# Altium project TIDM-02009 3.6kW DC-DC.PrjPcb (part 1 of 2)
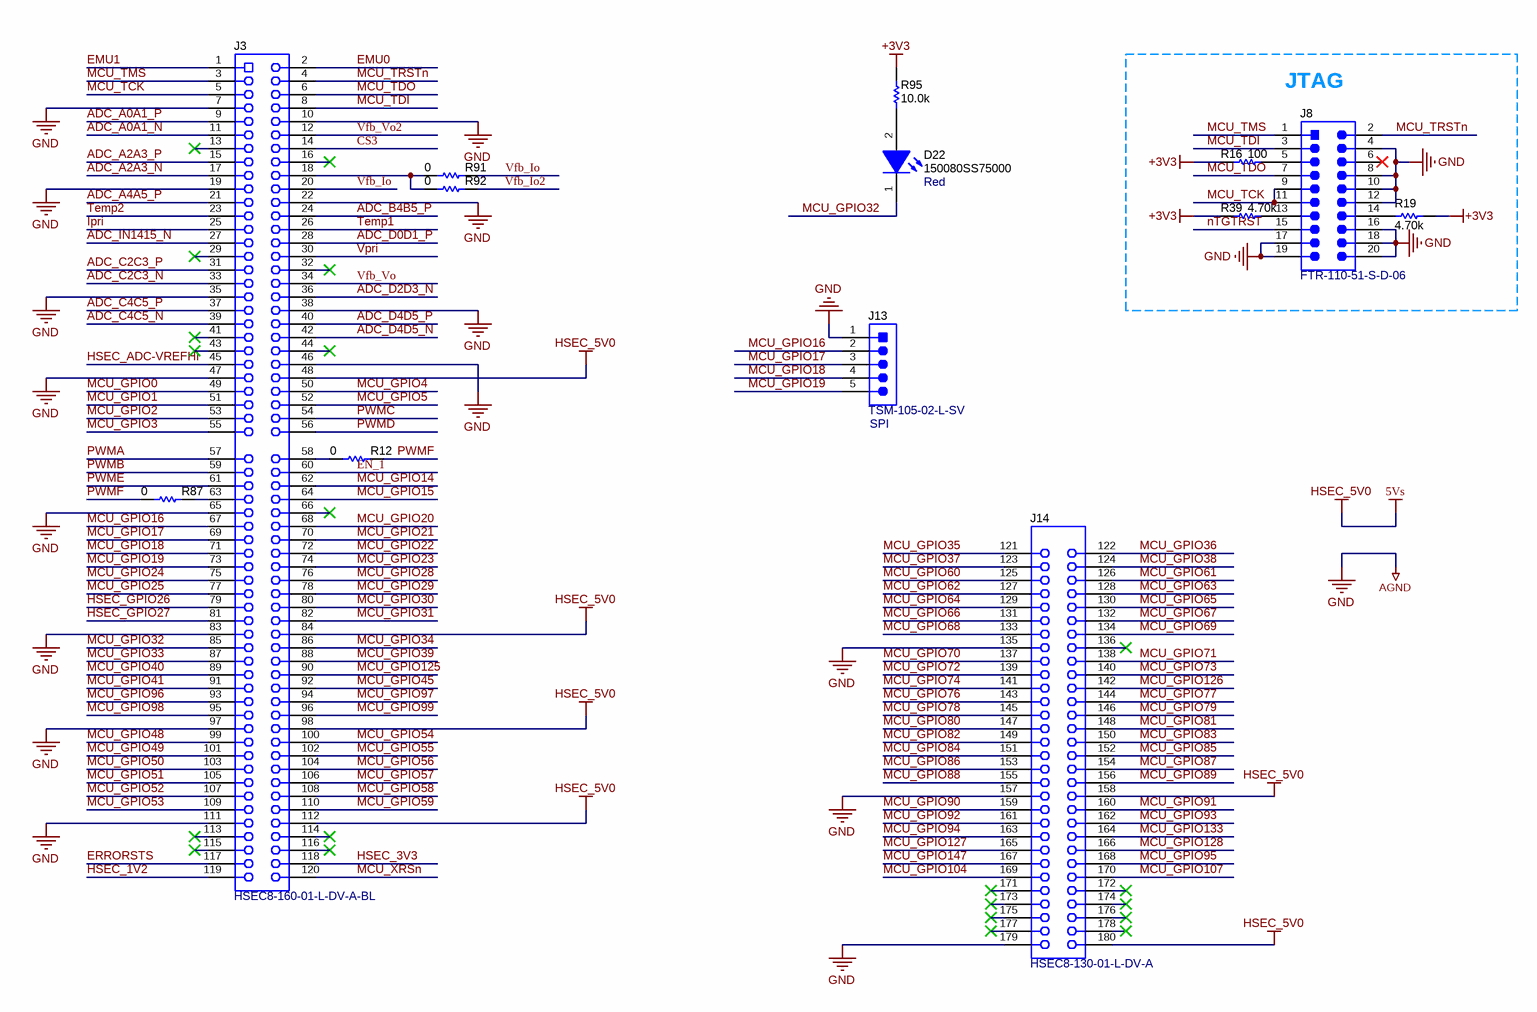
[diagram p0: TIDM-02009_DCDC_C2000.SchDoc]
CopyrightYear: 2020; PCB_Layout: H. Zhang, J. Cao, X. Gong; PCB_Rev: E2; PRJ_Customer: Public Release; PRJ_Engineer: H. Zhang; PRJ_Number: TIDM-02009; PRJ_Title: TIDM-02009 3.6kW DC-DC; SCH_Rev: E2; TechSupport: http://www.ti.com/support; TID: TIDM-02009
4 sheets, 301 parts. Net scope: global (net labels, ports and power ports of the same name join across sheets).
Board file: TIDM-02009 3.6kW DC-DC.PcbDoc
Sheets:
  TIDM-02009_DCDC_C2000.SchDoc
  TIDM-02009_DCDC_Control.SchDoc
  TIDM-02009_DCDC_Hardware.SchDoc
  TIDM-02009_DCDC_Power Stage.SchDoc

## Sheet TIDM-02009_DCDC_C2000.SchDoc
size A3; Date: Not shown in title block; ApprovedBy: Not shown in title block; CheckedBy: Not shown in title block; Author: Not shown in title block; CompanyName: Not shown in title block; Engineer: Not shown in title block; Organization: Not shown in title block; Address1: Not shown in title block; Address2: Not shown in title block; Address3: Not shown in title block; Address4: Not shown in title block; DocumentNumber: 2; Revision: Use project parameter SCH_Rev; SheetNumber: 2; SheetTotal: 3; PageSetup: Record=PageOptions¦CenterHorizontal=True¦CenterVertical=True¦PrintScale=1.00¦XCorrection=1.00¦YCorrection=1.00¦PrintKind=0¦BorderSize=5000000¦LeftOffset=0¦BottomOffset=0¦Orientation=2¦PaperLength=1000¦PaperWidth=1000¦Scale=100¦PaperSource=15¦PrintQuality=600¦MediaType=1¦DitherType=10¦PaperKind=Letter¦PrintScaleMode=1

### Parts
D22  150080SS75000  value Red  [WL-SMCW_RED_0805]
J3  HSEC8-160-01-L-DV-A-BL  [controlCARD-120HSEC]
J8  FTR-110-51-S-D-06  [Samtec_FTR-110-51-x-D-06]
J13  TSM-105-02-L-SV  [Samtec_TSM-105-02-x-SV]
J14  HSEC8-130-01-L-DV-A  [controlCARD-180HSEC-60pinAddon]
R12  ValueDisplayed: 0  [0603]  (hidden comment: RCS06030000Z0EA)
R16  ValueDisplayed: 100  [0603]  (hidden comment: ERJ-3EKF1000V)
R19  ValueDisplayed: 4.70k  [0603]  (hidden comment: RC0603FR-074K7L)
R39  ValueDisplayed: 4.70k  [0603]  (hidden comment: RC0603FR-074K7L)
R87  ValueDisplayed: 0  [0603]  (hidden comment: RCS06030000Z0EA)
R91  ValueDisplayed: 0  [0603]  (hidden comment: RCS06030000Z0EA)
R92  ValueDisplayed: 0  [0603]  (hidden comment: RCS06030000Z0EA)
R95  ValueDisplayed: 10.0k  [0603]  (hidden comment: RC0603FR-0710KL)

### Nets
5Vs: J3.48 J3.84 J3.98 J3.112 J14.158 J14.180  [also labelled HSEC_5V0]
+3V3: R16.1 R19.2 R39.1 R95.2
AGND: J3.7 J3.10 J3.19 J3.22 J3.35 J3.38 J3.46 J3.47 J3.65 J3.83 J3.97 J3.111 J8.4 J8.8 J8.10 J8.12 J8.16 J8.17 J8.18 J8.19 J8.20 J13.1 J14.135 J14.157 J14.179  [also labelled GND]
ADC_A0A1_N: J3.11
ADC_A0A1_P: J3.9
ADC_A2A3_N: J3.17
ADC_A2A3_P: J3.15
ADC_A4A5_P: J3.21
ADC_B4B5_P: J3.24
ADC_C2C3_N: J3.33
ADC_C2C3_P: J3.31
ADC_C4C5_N: J3.39
ADC_C4C5_P: J3.37
ADC_D0D1_P: J3.28
ADC_D2D3_N: J3.36
ADC_D4D5_N: J3.42
ADC_D4D5_P: J3.40
ADC_IN1415_N: J3.27
CS3: J3.14
EMU0: J3.2
EMU1: J3.1
EN_1: J3.60
ERRORSTS: J3.117
HSEC_1V2: J3.119
HSEC_3V3: J3.118
HSEC_ADC-VREFHI: J3.45
HSEC_GPIO26: J3.79
HSEC_GPIO27: J3.81
Ipri: J3.25
MCU_GPIO0: J3.49
MCU_GPIO1: J3.51
MCU_GPIO2: J3.53
MCU_GPIO3: J3.55
MCU_GPIO4: J3.50
MCU_GPIO5: J3.52
MCU_GPIO14: J3.62
MCU_GPIO15: J3.64
MCU_GPIO16: J3.67 J13.2
MCU_GPIO17: J3.69 J13.3
MCU_GPIO18: J3.71 J13.4
MCU_GPIO19: J3.73 J13.5
MCU_GPIO20: J3.68
MCU_GPIO21: J3.70
MCU_GPIO22: J3.72
MCU_GPIO23: J3.74
MCU_GPIO24: J3.75
MCU_GPIO25: J3.77
MCU_GPIO28: J3.76
MCU_GPIO29: J3.78
MCU_GPIO30: J3.80
MCU_GPIO31: J3.82
MCU_GPIO32: D22.1(K) J3.85
MCU_GPIO33: J3.87
MCU_GPIO34: J3.86
MCU_GPIO35: J14.121
MCU_GPIO36: J14.122
MCU_GPIO37: J14.123
MCU_GPIO38: J14.124
MCU_GPIO39: J3.88
MCU_GPIO40: J3.89
MCU_GPIO41: J3.91
MCU_GPIO45: J3.92
MCU_GPIO48: J3.99
MCU_GPIO49: J3.101
MCU_GPIO50: J3.103
MCU_GPIO51: J3.105
MCU_GPIO52: J3.107
MCU_GPIO53: J3.109
MCU_GPIO54: J3.100
MCU_GPIO55: J3.102
MCU_GPIO56: J3.104
MCU_GPIO57: J3.106
MCU_GPIO58: J3.108
MCU_GPIO59: J3.110
MCU_GPIO60: J14.125
MCU_GPIO61: J14.126
MCU_GPIO62: J14.127
MCU_GPIO63: J14.128
MCU_GPIO64: J14.129
MCU_GPIO65: J14.130
MCU_GPIO66: J14.131
MCU_GPIO67: J14.132
MCU_GPIO68: J14.133
MCU_GPIO69: J14.134
MCU_GPIO70: J14.137
MCU_GPIO71: J14.138
MCU_GPIO72: J14.139
MCU_GPIO73: J14.140
MCU_GPIO74: J14.141
MCU_GPIO76: J14.143
MCU_GPIO77: J14.144
MCU_GPIO78: J14.145
MCU_GPIO79: J14.146
MCU_GPIO80: J14.147
MCU_GPIO81: J14.148
MCU_GPIO82: J14.149
MCU_GPIO83: J14.150
MCU_GPIO84: J14.151
MCU_GPIO85: J14.152
MCU_GPIO86: J14.153
MCU_GPIO87: J14.154
MCU_GPIO88: J14.155
MCU_GPIO89: J14.156
MCU_GPIO90: J14.159
MCU_GPIO91: J14.160
MCU_GPIO92: J14.161
MCU_GPIO93: J14.162
MCU_GPIO94: J14.163
MCU_GPIO95: J14.168
MCU_GPIO96: J3.93
MCU_GPIO97: J3.94
MCU_GPIO98: J3.95
MCU_GPIO99: J3.96
MCU_GPIO104: J14.169
MCU_GPIO107: J14.170
MCU_GPIO125: J3.90
MCU_GPIO126: J14.142
MCU_GPIO127: J14.165
MCU_GPIO128: J14.166
MCU_GPIO133: J14.164
MCU_GPIO147: J14.167
MCU_TCK: J3.5 J8.9 J8.11
MCU_TDI: J3.8 J8.3
MCU_TDO: J3.6 J8.7
MCU_TMS: J3.3 J8.1
MCU_TRSTn: J3.4 J8.2
MCU_XRSn: J3.120
nTGTRST: J8.15
PWMA: J3.57
PWMB: J3.59
PWMC: J3.54
PWMD: J3.56
PWME: J3.61
PWMF: R12.2 R87.1
Temp1: J3.26
Temp2: J3.23
Vfb_Io: J3.20 R91.2
Vfb_Io2: R92.2
Vfb_Vo: J3.34
Vfb_Vo2: J3.12
Vpri: J3.30
NetD22_2: D22.2(A) R95.1
NetJ3_18: J3.18 R91.1 R92.1
NetJ3_58: J3.58 R12.1
NetJ3_63: J3.63 R87.2
NetJ8_5: J8.5 R16.2
NetJ8_13: J8.13 R39.2
NetJ8_14: J8.14 R19.1

Not connected (* = marked no-connect by the designer): J3 13* 16* 29* 32* 41* 43* 44* 66* 113* 114* 115* 116*; J8 6*; J14 136* 171* 172* 173* 174* 175* 176* 177* 178*

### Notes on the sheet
- (near J8) JTAG
- (near J13) SPI

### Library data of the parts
D22 = CMP-0002951-1: LED, Red, SMD; Manufacturer: Wurth Elektronik; Io_A: 30mA; Power_TotalModule: 72mW; Vr_V: 5V; Tjmax_C: 85°C; Value1: 0.072W; U/M: EA; Angle: 140; Ir_A: 25µA; Vf_V: 1.9V; Type: AlInGaP
J3 = CMP-0003814-2: C2000 controlCARD-120HSEC connector, SMT; Manufacturer: Samtec; Note: The pin numbering does not match Samtec datasheet
J8 = CMP-0075640-2: Header, 1.27mm, 10x2, Tin, SMT; Manufacturer: Samtec; Pitch_mm: 1.27; Gender: Male; Cert_UL: Y; Green_REACh: Passed; Current_A: 3.1A; Shrouded: N; RowSpacing_mm: 2.54; Green_Lifecycle: Active; Row_Count: 2
J13 = CMP-0081122-1: Header, 2.54mm, 5x1, Gold with Tin tail, SMT; Manufacturer: Samtec; Pitch_mm: 2.54; Gender: Male; Cert_UL: Y; Current_A: 5.4A; Voltage_V: 475V; Shrouded: N; Row_Count: 1
J14 = CMP-0003859-2: C2000 controlCARD-180HSEC (60-pin addon) connector, SMT; Manufacturer: Samtec; Note: The pin numbering does not match Samtec datasheet
R12 R87 R91 R92 = CMP-0081973-1: RES, 0, 0%, 0.25 W, AEC-Q200 Grade 0, 0603; Manufacturer: Vishay-Dale; SizeAreaWB_mm2: 4.68; SizeArea_mm2: 1.28; AEC Qualified: Y; AEC Category: Q200; Value: 0; SizeZ_mm: 1; SizeY_mm: 0.8; Power_W: 250mW; Value2: 0.25W; SizeX_mm: 1.6
R16 = CMP-0022679-3: RES, 100, 1%, 0.1 W, AEC-Q200 Grade 0, 0603; Manufacturer: Panasonic; Power_W: 100mW; TempCo: 100 ppm/C; Value_Code: 100R; U/M: EA; Value: 100; EIA_Code: E96; SizeX_mm: 1.6; SizeY_mm: 0.8; SizeZ_mm: 1; Value2: 0.1W; SizeArea_mm2: 1.28; AEC Qualified: Y; AEC Grade: 0; AEC Category: Q200
R19 R39 = CMP-0023153-5: RES, 4.70 k, 1%, 0.1 W, 0603; Manufacturer: Yageo; Power_W: 100mW; TempCo: 100 ppm/C; Value_Code: 4k70; Value: 4.70k; Res_ohm: 4.7k; SizeX_mm: 1.6; SizeY_mm: 0.8; SizeZ_mm: 1; Value2: 0.1W; SizeArea_mm2: 1.28; AEC Qualified: N; VDC_V: 75V; AEC Category: Q200; SizeAreaWB_mm2: 4.68
R95 = CMP-0022746-5: RES, 10.0 k, 1%, 0.1 W, 0603; Manufacturer: Yageo; Power_W: 100mW; TempCo: 100 ppm/C; Value_Code: 10k0; Value: 10.0k; EIA_Code: E96; Res_ohm: 10k; SizeX_mm: 1.6; SizeY_mm: 0.8; SizeZ_mm: 1; Value2: 0.1W; SizeArea_mm2: 1.28; AEC Qualified: N; VDC_V: 75V; AEC Category: Q200; SizeAreaWB_mm2: 4.68

## Sheet TIDM-02009_DCDC_Control.SchDoc
size A2; PageSetup: Record=PageOptions¦CenterHorizontal=True¦CenterVertical=True¦PrintScale=0.69¦XCorrection=1.00¦YCorrection=1.00¦PrintKind=0¦BorderSize=5000000¦LeftOffset=0¦BottomOffset=0¦Orientation=2¦PaperLength=1000¦PaperWidth=1000¦Scale=100¦PaperSource=15¦PrintQuality=600¦MediaType=1¦DitherType=10¦PaperKind=Letter¦PrintScaleMode=1
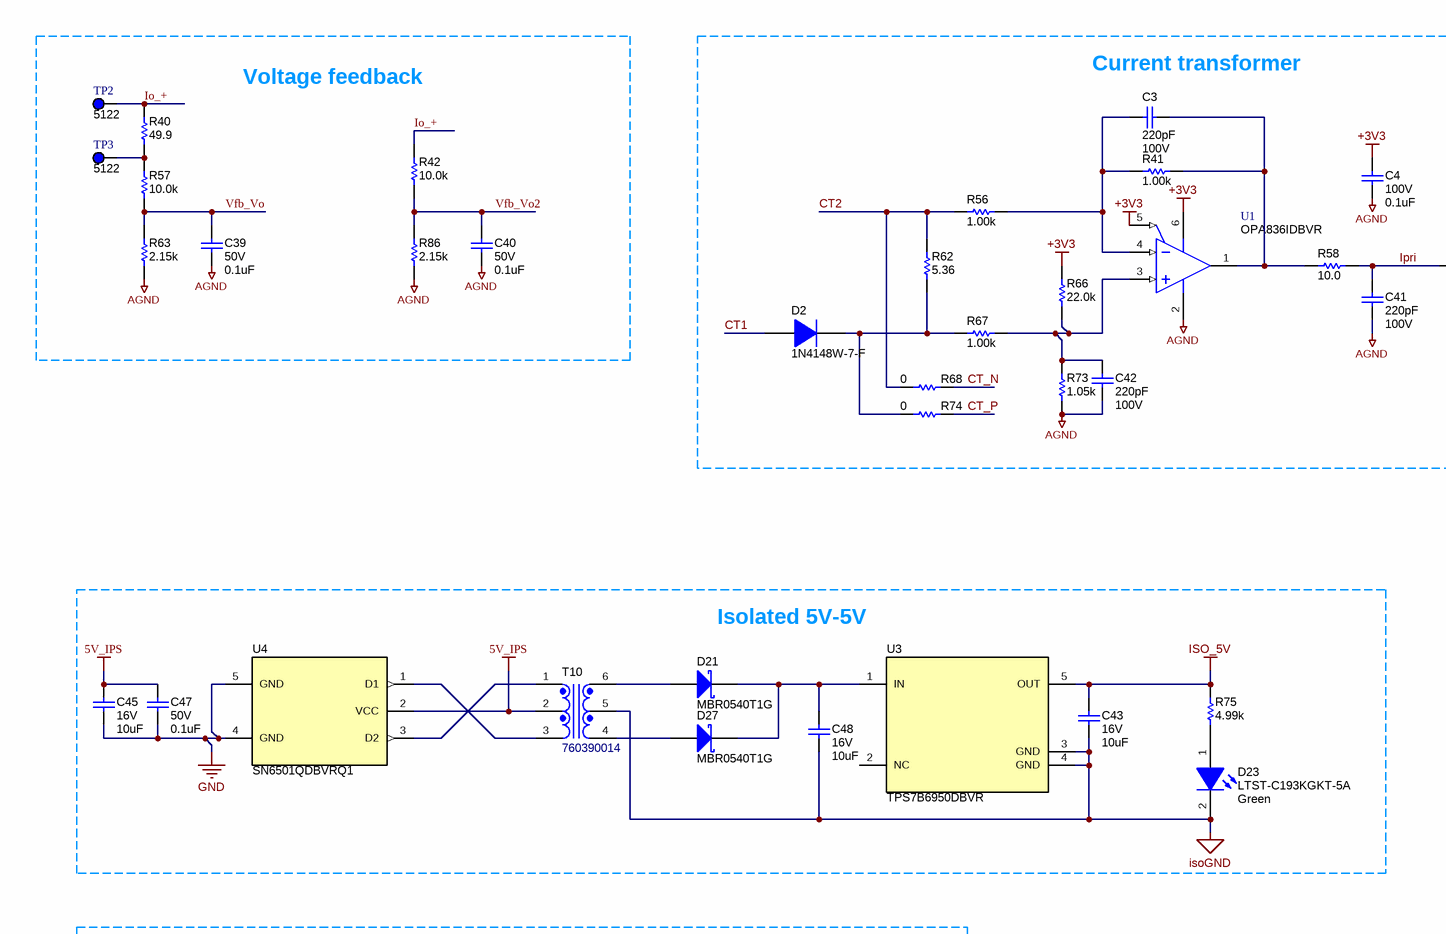
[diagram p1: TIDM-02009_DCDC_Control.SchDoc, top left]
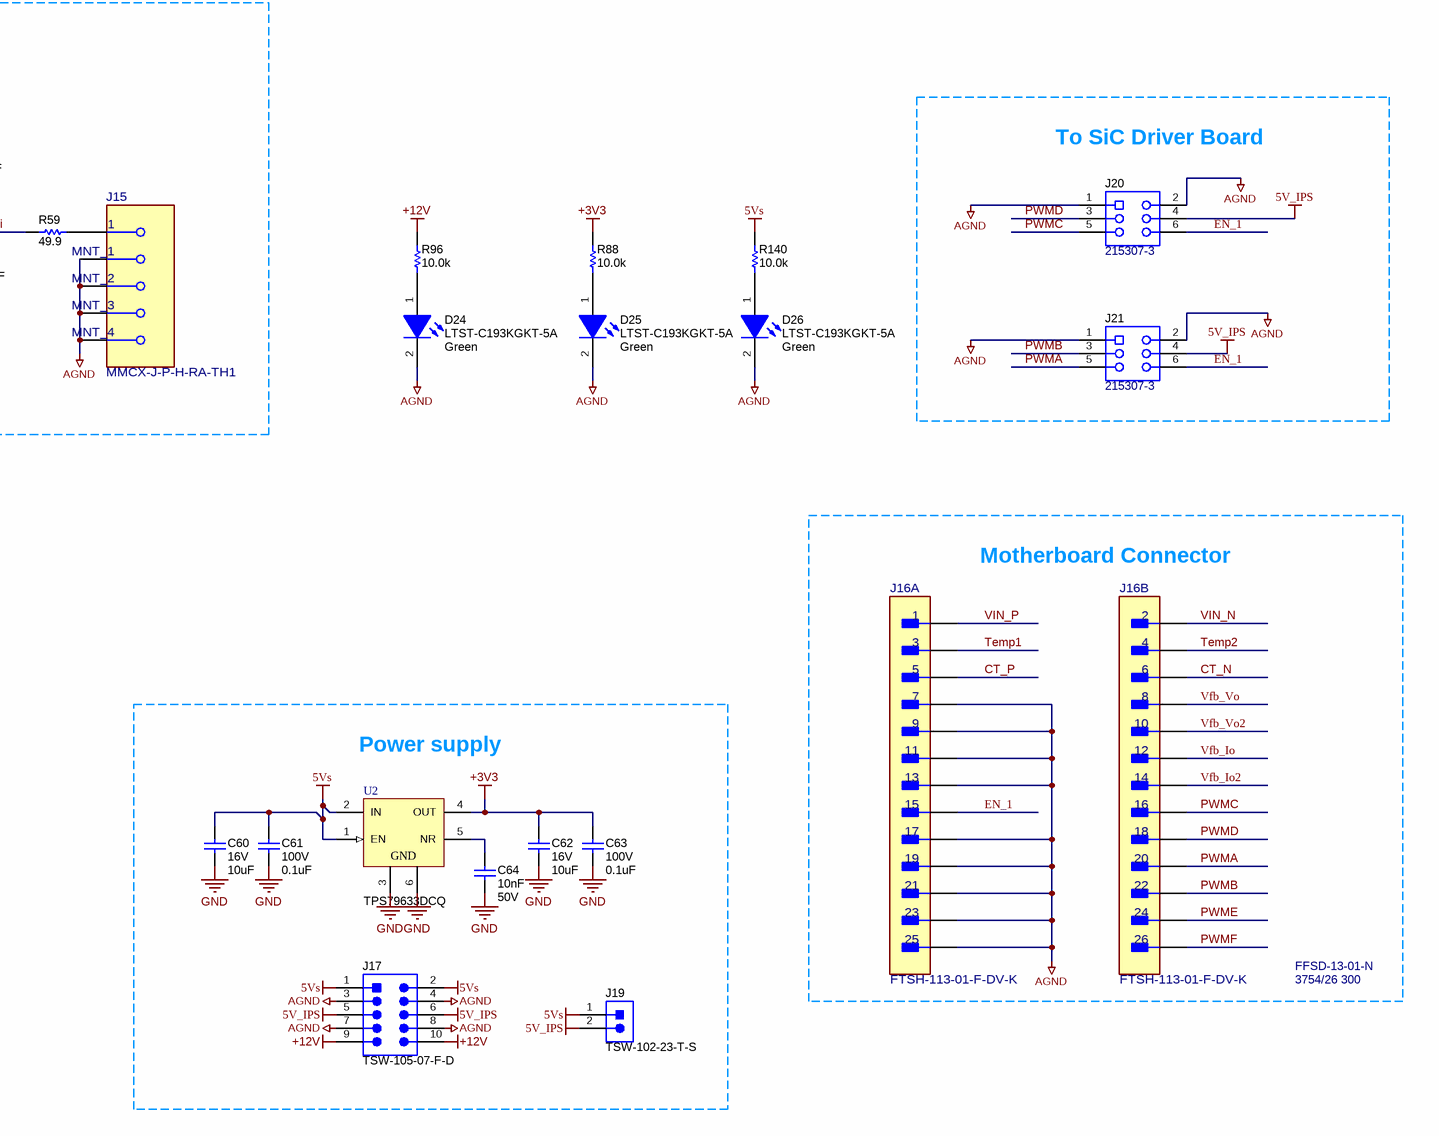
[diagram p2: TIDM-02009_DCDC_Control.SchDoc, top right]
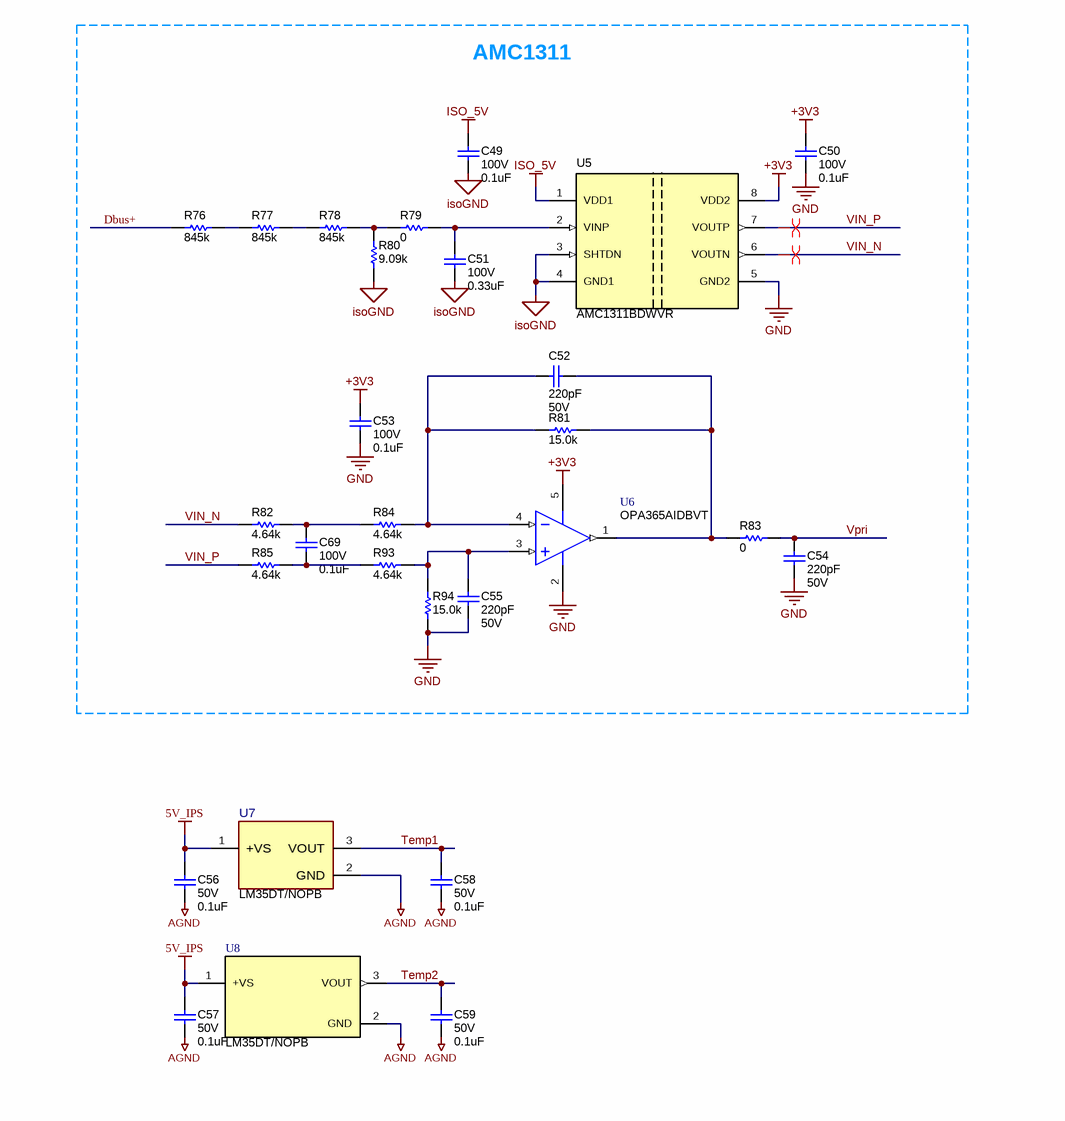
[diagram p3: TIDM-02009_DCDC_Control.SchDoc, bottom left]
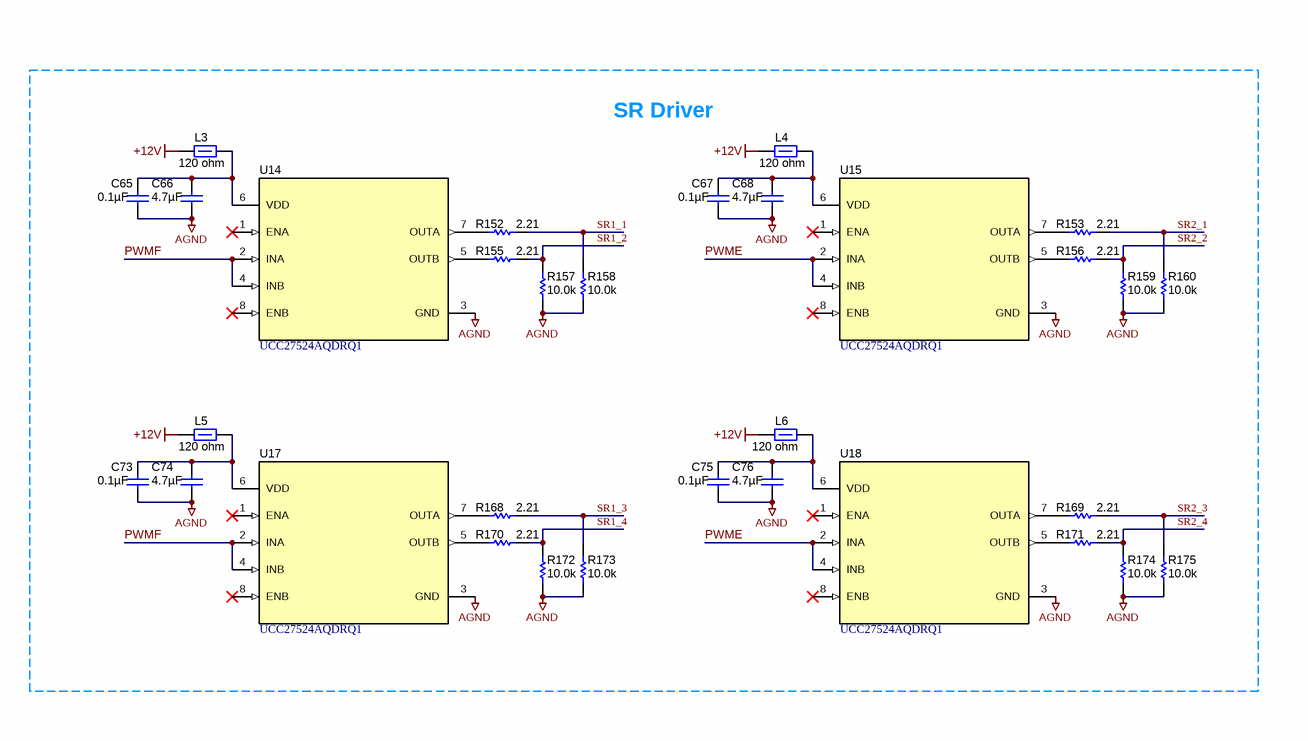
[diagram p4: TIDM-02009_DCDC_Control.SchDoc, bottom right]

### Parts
C3  Cap_F: 220pF  VDC_V: 100V  [0603]  (hidden comment: GRM188R72A221KA01D)
C4  VDC_V: 100V  ValueDisplayed: 0.1uF  [0603]  (hidden comment: GRM188R72A104KA35D)
C39  VDC_V: 50V  ValueDisplayed: 0.1uF  [0805_150]  (hidden comment: CEU4J2X7R1H104K125AE)
C40  VDC_V: 50V  ValueDisplayed: 0.1uF  [0805_150]  (hidden comment: CEU4J2X7R1H104K125AE)
C41  Cap_F: 220pF  VDC_V: 100V  [0603]  (hidden comment: GRM188R72A221KA01D)
C42  Cap_F: 220pF  VDC_V: 100V  [0603]  (hidden comment: GRM188R72A221KA01D)
C43  VDC_V: 16V  ValueDisplayed: 10uF  [0805_HV]  (hidden comment: CL21B106KOQNNNE)
C45  VDC_V: 16V  ValueDisplayed: 10uF  [0805_HV]  (hidden comment: CL21B106KOQNNNE)
C47  VDC_V: 50V  ValueDisplayed: 0.1uF  [0805_150]  (hidden comment: CEU4J2X7R1H104K125AE)
C48  VDC_V: 16V  ValueDisplayed: 10uF  [0805_HV]  (hidden comment: CL21B106KOQNNNE)
C49  VDC_V: 100V  ValueDisplayed: 0.1uF  [0603]  (hidden comment: GRM188R72A104KA35D)
C50  VDC_V: 100V  ValueDisplayed: 0.1uF  [0603]  (hidden comment: GRM188R72A104KA35D)
C51  VDC_V: 100V  ValueDisplayed: 0.33uF  [1206_150]  (hidden comment: C3216X7R2A334K130AA)
C52  Cap_F: 220pF  VDC_V: 50V  [0603]  (hidden comment: C0603X221K5RACTU)
C53  VDC_V: 100V  ValueDisplayed: 0.1uF  [0603]  (hidden comment: GRM188R72A104KA35D)
C54  Cap_F: 220pF  VDC_V: 50V  [0603]  (hidden comment: C0603X221K5RACTU)
C55  Cap_F: 220pF  VDC_V: 50V  [0603]  (hidden comment: C0603X221K5RACTU)
C56  VDC_V: 50V  ValueDisplayed: 0.1uF  [0805_150]  (hidden comment: CEU4J2X7R1H104K125AE)
C57  VDC_V: 50V  ValueDisplayed: 0.1uF  [0805_150]  (hidden comment: CEU4J2X7R1H104K125AE)
C58  VDC_V: 50V  ValueDisplayed: 0.1uF  [0805_150]  (hidden comment: CEU4J2X7R1H104K125AE)
C59  VDC_V: 50V  ValueDisplayed: 0.1uF  [0805_150]  (hidden comment: CEU4J2X7R1H104K125AE)
C60  VDC_V: 16V  ValueDisplayed: 10uF  [0805_HV]  (hidden comment: CL21B106KOQNNNE)
C61  VDC_V: 100V  ValueDisplayed: 0.1uF  [0603]  (hidden comment: GRM188R72A104KA35D)
C62  VDC_V: 16V  ValueDisplayed: 10uF  [0805_HV]  (hidden comment: CL21B106KOQNNNE)
C63  VDC_V: 100V  ValueDisplayed: 0.1uF  [0603]  (hidden comment: GRM188R72A104KA35D)
C64  Cap_F: 10nF  VDC_V: 50V  [0603]  (hidden comment: GCM188R71H103KA37D)
C65  ValueDisplayed: 0.1µF  [0603]  (hidden comment: CGA3E2X7R1E104K080AA)
C66  ValueDisplayed: 4.7µF  [1206]  (hidden comment: GRM319R61H475KA12)
C67  ValueDisplayed: 0.1µF  [0603]  (hidden comment: CGA3E2X7R1E104K080AA)
C68  ValueDisplayed: 4.7µF  [1206]  (hidden comment: GRM319R61H475KA12)
C69  VDC_V: 100V  ValueDisplayed: 0.1uF  [0603]  (hidden comment: GRM188R72A104KA35D)
C73  ValueDisplayed: 0.1µF  [0603]  (hidden comment: CGA3E2X7R1E104K080AA)
C74  ValueDisplayed: 4.7µF  [1206]  (hidden comment: GRM319R61H475KA12)
C75  ValueDisplayed: 0.1µF  [0603]  (hidden comment: CGA3E2X7R1E104K080AA)
C76  ValueDisplayed: 4.7µF  [1206]  (hidden comment: GRM319R61H475KA12)
D2  1N4148W-7-F  [SOD-123]
D21  MBR0540T1G  [SOD-123]
D23  LTST-C193KGKT-5A  value Green  [LTST-C193_Green]
D24  LTST-C193KGKT-5A  value Green  [LTST-C193_Green]
D25  LTST-C193KGKT-5A  value Green  [LTST-C193_Green]
D26  LTST-C193KGKT-5A  value Green  [LTST-C193_Green]
D27  MBR0540T1G  [SOD-123]
J15  MMCX-J-P-H-RA-TH1  [FP-MMCX-J-P-H-RA-TH1_PTH_CONN_JACK-MFG]
J16  FTSH-113-01-F-DV-K  [FP-FTSH-113-01-F-DV-K_HDR26-MFG]  (parts A,B of 2)
J17  TSW-105-07-F-D  [Samtec_TSW-105-07-x-D]
J19  TSW-102-23-T-S  [Samtec_TSW-102-23-X-S]
J20  215307-3  [TE_215307-3]
J21  215307-3  [TE_215307-3]
L3  ValueDisplayed: 120 ohm  [0603]  (hidden comment: 74279262)
L4  ValueDisplayed: 120 ohm  [0603]  (hidden comment: 74279262)
L5  ValueDisplayed: 120 ohm  [0603]  (hidden comment: 74279262)
L6  ValueDisplayed: 120 ohm  [0603]  (hidden comment: 74279262)
R40  ValueDisplayed: 49.9  [0603]  (hidden comment: RC0603FR-0749R9L)
R41  ValueDisplayed: 1.00k  [0603]  (hidden comment: RC0603FR-071KL)
R42  ValueDisplayed: 10.0k  [0603]  (hidden comment: RC0603FR-0710KL)
R56  ValueDisplayed: 1.00k  [0603]  (hidden comment: RC0603FR-071KL)
R57  ValueDisplayed: 10.0k  [0603]  (hidden comment: RC0603FR-0710KL)
R58  ValueDisplayed: 10.0  [0603]  (hidden comment: RC0603FR-0710RL)
R59  ValueDisplayed: 49.9  [0603]  (hidden comment: RC0603FR-0749R9L)
R62  ValueDisplayed: 5.36  [1206]  (hidden comment: CRCW12065R36FKEA)
R63  ValueDisplayed: 2.15k  [0603]  (hidden comment: RC0603FR-072K15L)
R66  ValueDisplayed: 22.0k  [0603]  (hidden comment: ERJ-3EKF2202V)
R67  ValueDisplayed: 1.00k  [0603]  (hidden comment: RC0603FR-071KL)
R68  ValueDisplayed: 0  [0603]  (hidden comment: RCS06030000Z0EA)
R73  ValueDisplayed: 1.05k  [0603]  (hidden comment: RC0603FR-071K05L)
R74  ValueDisplayed: 0  [0603]  (hidden comment: RCS06030000Z0EA)
R75  ValueDisplayed: 4.99k  [0603]  (hidden comment: CR0603-FX-4991ELF)
R76  ValueDisplayed: 845k  [1206]  (hidden comment: ERJ-8ENF8453V)
R77  ValueDisplayed: 845k  [1206]  (hidden comment: ERJ-8ENF8453V)
R78  ValueDisplayed: 845k  [1206]  (hidden comment: ERJ-8ENF8453V)
R79  ValueDisplayed: 0  [0603]  (hidden comment: RCS06030000Z0EA)
R80  ValueDisplayed: 9.09k  [1206]  (hidden comment: ERJ-8ENF9091V)
R81  ValueDisplayed: 15.0k  [0603]  (hidden comment: RC0603FR-0715KL)
R82  ValueDisplayed: 4.64k  [0603]  (hidden comment: RC0603FR-074K64L)
R83  ValueDisplayed: 0  [0603]  (hidden comment: RCS06030000Z0EA)
R84  ValueDisplayed: 4.64k  [0603]  (hidden comment: RC0603FR-074K64L)
R85  ValueDisplayed: 4.64k  [0603]  (hidden comment: RC0603FR-074K64L)
R86  ValueDisplayed: 2.15k  [0603]  (hidden comment: RC0603FR-072K15L)
R88  ValueDisplayed: 10.0k  [0603]  (hidden comment: RC0603FR-0710KL)
R93  ValueDisplayed: 4.64k  [0603]  (hidden comment: RC0603FR-074K64L)
R94  ValueDisplayed: 15.0k  [0603]  (hidden comment: RC0603FR-0715KL)
R96  ValueDisplayed: 10.0k  [0603]  (hidden comment: RC0603FR-0710KL)
R140  ValueDisplayed: 10.0k  [0603]  (hidden comment: RC0603FR-0710KL)
R152  ValueDisplayed: 2.21  [0603L]  (hidden comment: CRCW06032R21FKEA)
R153  ValueDisplayed: 2.21  [0603L]  (hidden comment: CRCW06032R21FKEA)
R155  ValueDisplayed: 2.21  [0603L]  (hidden comment: CRCW06032R21FKEA)
R156  ValueDisplayed: 2.21  [0603L]  (hidden comment: CRCW06032R21FKEA)
R157  ValueDisplayed: 10.0k  [0603L]  (hidden comment: CRCW060310K0FKEA)
R158  ValueDisplayed: 10.0k  [0603L]  (hidden comment: CRCW060310K0FKEA)
R159  ValueDisplayed: 10.0k  [0603L]  (hidden comment: CRCW060310K0FKEA)
R160  ValueDisplayed: 10.0k  [0603L]  (hidden comment: CRCW060310K0FKEA)
R168  ValueDisplayed: 2.21  [0603L]  (hidden comment: CRCW06032R21FKEA)
R169  ValueDisplayed: 2.21  [0603L]  (hidden comment: CRCW06032R21FKEA)
R170  ValueDisplayed: 2.21  [0603L]  (hidden comment: CRCW06032R21FKEA)
R171  ValueDisplayed: 2.21  [0603L]  (hidden comment: CRCW06032R21FKEA)
R172  ValueDisplayed: 10.0k  [0603L]  (hidden comment: CRCW060310K0FKEA)
R173  ValueDisplayed: 10.0k  [0603L]  (hidden comment: CRCW060310K0FKEA)
R174  ValueDisplayed: 10.0k  [0603L]  (hidden comment: CRCW060310K0FKEA)
R175  ValueDisplayed: 10.0k  [0603L]  (hidden comment: CRCW060310K0FKEA)
T10  760390014  [Wurth_760390013]
TP2  5122  [Keystone5122]
TP3  5122  [Keystone5122]
U1  OPA836IDBVR  [DBV0006A_L]
U2  TPS79633DCQ  [DCQ0006A_N]
U3  TPS7B6950DBVR  [DBV0005A_N]
U4  SN6501QDBVRQ1  [DBV0005A_L]
U5  AMC1311BDWVR  [DWV0008A]
U6  OPA365AIDBVT  [DBV0005A_N]
U7  LM35DT/NOPB  [FP-LM35DT-NOPB-Recommended_Land_Pattern_hr]
U8  LM35DT/NOPB  [NEB0003F]
U14  UCC27524AQDRQ1  [D0008A_N]
U15  UCC27524AQDRQ1  [D0008A_N]
U17  UCC27524AQDRQ1  [D0008A_N]
U18  UCC27524AQDRQ1  [D0008A_N]

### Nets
5V_IPS: C45.1 C47.1 C56.1 C57.1 J17.5 J17.6 J19.2 J20.4 J21.4 T10.2 U4.2(VCC) U7.1(+VS) U8.1(+VS)
5Vs: C60.1 C61.1 J17.1 J17.2 J19.1 R140.2 U2.1(EN) U2.2(IN)
+3V3: C4.1 C50.1 C53.1 C62.1 C63.1 R66.2 R88.2 U1.5(~{PD}) U1.6(VS+) U2.4(OUT) U5.8(VDD2) U6.5(V+)
+12V: J17.9 J17.10 L3.1 L4.1 L5.1 L6.1 R96.2
AGND: C4.2 C39.2 C40.2 C41.2 C42.2 C45.2 C47.2 C50.2 C53.2 C54.2 C55.2 C56.2 C57.2 C58.2 C59.2 C60.2 C61.2 C62.2 C63.2 C64.2 C65.2 C66.2 C67.2 C68.2 C73.2 C74.2 C75.2 C76.2 D24.2(K) D25.2(K) D26.2(K) J15.2(MNT_1) J15.3(MNT_2) J15.4(MNT_3) J15.5(MNT_4) J16.7 J16.9 J16.11 J16.13 J16.17 J16.19 J16.21 J16.23 J16.25 J17.3 J17.4 J17.7 J17.8 J20.1 J20.2 J21.1 J21.2 R63.1 R73.1 R86.1 R94.1 R157.1 R158.1 R159.1 R160.1 R172.1 R173.1 R174.1 R175.1 U1.2(VS-) U2.3(GND) U2.6(GND) U4.4(GND) U4.5(GND) U5.5(GND2) U6.2(V-) U7.2(GND) U8.2(GND) U14.3(GND) U15.3(GND) U17.3(GND) U18.3(GND)  [also labelled GND]
ISO_5V: C43.1 C49.1 R75.2 U3.5(OUT) U5.1(VDD1)
isoGND: C43.2 C48.2 C49.2 C51.2 D23.2(K) R80.1 T10.5 U3.3(GND) U3.4(GND) U5.3(SHTDN) U5.4(GND1)
CT1: D2.2(A)
CT2: R56.1 R62.2 R68.1
CT_N: J16.6 R68.2
CT_P: J16.5 R74.2
Dbus+: R76.1
EN_1: J16.15 J20.6 J21.6
Io_+: R40.2 R42.2 TP2.1
Ipri: C41.1 R58.2 R59.1
PWMA: J16.20 J21.5
PWMB: J16.22 J21.3
PWMC: J16.16 J20.5
PWMD: J16.18 J20.3
PWME: J16.24 U15.2(INA) U15.4(INB) U18.2(INA) U18.4(INB)
PWMF: J16.26 U14.2(INA) U14.4(INB) U17.2(INA) U17.4(INB)
SR1_1: R152.2 R158.2
SR1_2: R155.2 R157.2
SR1_3: R168.2 R173.2
SR1_4: R170.2 R172.2
SR2_1: R153.2 R160.2
SR2_2: R156.2 R159.2
SR2_3: R169.2 R175.2
SR2_4: R171.2 R174.2
Temp1: C58.1 J16.3 U7.3(VOUT)
Temp2: C59.1 J16.4 U8.3(VOUT)
Vfb_Io: J16.12
Vfb_Io2: J16.14
Vfb_Vo: C39.1 J16.8 R57.1 R63.2
Vfb_Vo2: C40.1 J16.10 R42.1 R86.2
VIN_N: J16.2 R82.1 U5.6(VOUTN)
VIN_P: J16.1 R85.1 U5.7(VOUTP)
Vpri: C54.1 R83.2
NetC3_1: C3.1 R41.2 R58.1 U1.1(VOUT)
NetC3_2: C3.2 R41.1 R56.2 U1.4(VIN-)
NetC42_1: C42.1 R66.1 R67.2 R73.2 U1.3(VIN+)
NetC48_1: C48.1 D21.1(K) D27.1(K) U3.1(IN)
NetC51_1: C51.1 R79.2 U5.2(VINP)
NetC52_1: C52.1 R81.2 R83.1 U6.1(VOUT)
NetC52_2: C52.2 R81.1 R84.2 U6.4(IN-)
NetC55_1: C55.1 R93.2 R94.2 U6.3(IN+)
NetC64_1: C64.1 U2.5(NR)
NetC65_1: C65.1 C66.1 L3.2 U14.6(VDD)
NetC67_1: C67.1 C68.1 L4.2 U15.6(VDD)
NetC69_1: C69.1 R82.2 R84.1
NetC69_2: C69.2 R85.2 R93.1
NetC73_1: C73.1 C74.1 L5.2 U17.6(VDD)
NetC75_1: C75.1 C76.1 L6.2 U18.6(VDD)
NetD2_1: D2.1(K) R62.1 R67.1 R74.1
NetD21_2: D21.2(A) T10.6
NetD23_1: D23.1(A) R75.1
NetD24_1: D24.1(A) R96.1
NetD25_1: D25.1(A) R88.1
NetD26_1: D26.1(A) R140.1
NetD27_2: D27.2(A) T10.4
NetJ15_1: J15.1 R59.2
NetR40_1: R40.1 R57.2 TP3.1
NetR76_2: R76.2 R77.1
NetR77_2: R77.2 R78.1
NetR78_2: R78.2 R79.1 R80.2
NetR152_1: R152.1 U14.7(OUTA)
NetR153_1: R153.1 U15.7(OUTA)
NetR155_1: R155.1 U14.5(OUTB)
NetR156_1: R156.1 U15.5(OUTB)
NetR168_1: R168.1 U17.7(OUTA)
NetR169_1: R169.1 U18.7(OUTA)
NetR170_1: R170.1 U17.5(OUTB)
NetR171_1: R171.1 U18.5(OUTB)
NetT10_1: T10.1 U4.3(D2)
NetT10_3: T10.3 U4.1(D1)

Not connected (* = marked no-connect by the designer): U3 2(NC); U14 1(ENA)* 8(ENB)*; U15 1(ENA)* 8(ENB)*; U17 1(ENA)* 8(ENB)*; U18 1(ENA)* 8(ENB)*

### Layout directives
differential pair: VIN_N, VIN_P

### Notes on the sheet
- Voltage feedback
- (near C3) Current transformer
- To SiC Driver Board
- Isolated 5V-5V
- Motherboard Connector
- Power supply
- AMC1311
- FFSD-13-01-N
- 3754/26 300
- SR Driver

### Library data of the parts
C3 C41 C42 = CMP-0007474-4: CAP, CERM, 220 pF, 100 V, +/- 10%, X7R, 0603; Manufacturer: MuRata; TaMin_C: -55°C; Polarized: N; SizeAreaWB_mm2: 4.68; Value1: Unknown; U/M: EA; Value: 220pF; TaMax_C: 125°C; SizeZ_mm: 1; SizeX_mm: 1.6; SizeY_mm: 0.8; SizeArea_mm2: 1.28; AEC Category: Q200
C4 C49 C50 C53 C61 C63 C69 = CMP-0007469-4: CAP, CERM, 0.1 uF, 100 V, +/- 10%, X7R, 0603; Manufacturer: MuRata; TaMin_C: -55°C; Polarized: N; SizeAreaWB_mm2: 4.68; Value1: Unknown; U/M: EA; Value: 0.1uF; TaMax_C: 125°C; SizeZ_mm: 1; SizeX_mm: 1.6; SizeY_mm: 0.8; SizeArea_mm2: 1.28; Cap_F: 100nF; AEC Category: Q200
C39 C40 C47 C56-C59 = CMP-0007961-2: CAP, CERM, 0.1 uF, 50 V, +/- 10%, X7R, AEC-Q200 Grade 1, 0805; Manufacturer: TDK; TaMin_C: -55°C; Polarized: N; SizeAreaWB_mm2: 6.75; Value1: Unknown; U/M: EA; Value: 0.1uF; TaMax_C: 125°C; SizeZ_mm: 1.5; SizeX_mm: 2; SizeY_mm: 1.25; Cap_Case: 0805; SizeArea_mm2: 2.5; CompType: Capacitor; AEC Qualified: Y; Cap_F: 100nF; AEC Grade: 1; AEC Category: Q200
C43 C48 C60 C62 = CMP-0007995-2: CAP, CERM, 10 uF, 16 V, +/- 10%, X7R, 0805; Manufacturer: Samsung Electro-Mechanics; TaMin_C: -55°C; Polarized: N; SizeAreaWB_mm2: 6.75; Value1: Unknown; U/M: EA; Value: 10uF; TaMax_C: 125°C; SizeZ_mm: 1.45; SizeX_mm: 2; SizeY_mm: 1.25; Cap_Case: 0805; SizeArea_mm2: 2.5; CompType: Capacitor; Cap_F: 10µF; AEC Category: Q200
C45 = CMP-0007995-2: CAP, CERM, 10 uF, 16 V, +/- 10%, X7R, 0805; Manufacturer: Samsung Electro-Mechanics; TaMin_C: -55°C; Polarized: N; SizeAreaWB_mm2: 6.75; Value1: Unknown; U/M: EA; Value: 10uF; TaMax_C: 125°C; SizeZ_mm: 1.45; SizeX_mm: 2; SizeY_mm: 1.25; Cap_Case: 0805; SizeArea_mm2: 2.5; Cap_F: 10µF; AEC Category: Q200
C51 = CMP-0008714-2: CAP, CERM, 0.33 uF, 100 V, +/- 10%, X7R,; Manufacturer: TDK; TaMin_C: -55°C; ESR_ohm: 0.011504; Polarized: N; SizeAreaWB_mm2: 10.92; Value1: 0.011504 ohm; U/M: EA; Value: 0.33uF; TaMax_C: 125°C; SizeZ_mm: 1.5; SizeX_mm: 3.2; SizeY_mm: 1.6; SizeArea_mm2: 5.12; Cap_F: 330nF; IRMS_A: 2.14919A; AEC Category: Q200
C52 C54 C55 = CMP-0006982-4: CAP, CERM, 220 pF, 50 V, +/- 10%, X7R, 0603; Manufacturer: Kemet; TaMin_C: -55°C; Polarized: N; SizeAreaWB_mm2: 4.68; Value1: Unknown; U/M: EA; Value: 220pF; TaMax_C: 125°C; SizeZ_mm: 1; SizeX_mm: 1.6; SizeY_mm: 0.8; SizeArea_mm2: 1.28; AEC Category: Q200
C64 = CMP-0007143-4: CAP, CERM, 0.01 uF, 50 V, +/- 10%, X7R, AEC-Q200 Grade 1, 0603; Manufacturer: MuRata; TaMin_C: -55°C; Polarized: N; SizeAreaWB_mm2: 4.68; Value1: Unknown; U/M: EA; Value: 0.01uF; TaMax_C: 125°C; SizeZ_mm: 1; SizeX_mm: 1.6; SizeY_mm: 0.8; SizeArea_mm2: 1.28; AEC Qualified: Y; AEC Category: Q200
C65 C67 C73 C75 = CGA3E2X7R1E104K080AA: CAP, CERM, 0.1 µF, 25 V,+/- 10%, X7R, AEC-Q200 Grade 1, 0603; Manufacturer: TDK; Polarized: N; CompType: Capacitor; Value: 0.1uF; U/M: EA; Cap_F: 0.0000001; Tolerance_%: 10; VDC_V: 25; Value2: 25V; TaMin_C: -55; TaMax_C: 125; SizeArea_mm2: 1.28; SizeAreaWB_mm2: 4.68; SizeX_mm: 1.6; SizeY_mm: 0.8; SizeZ_mm: 1; AEC Category: Q200; AEC Qualified: Y
C66 C68 C74 C76 = GRM319R61H475KA12: CAP, CERM, 4.7 µF, 50 V, +/- 10%, X5R, 1206; Manufacturer: MuRata; Polarized: N; CompType: Capacitor; Value: 4.7uF; U/M: EA; Cap_F: 0.0000047; Tolerance_%: 10; Value1: Unknown; VDC_V: 50; Value2: 50V; TaMin_C: -55; TaMax_C: 85; AEC Category: Q200
D2 = CMP-0029001-2: Diode, Ultrafast, 100 V, 0.15 A, SOD-123; Manufacturer: Diodes Inc.; SizeX_mm: 3.85; Value2: 1.25V; Green_REACh: Passed; TJmax_C: 150°C; AEC Category: Q101; SizeAreaWB_mm2: 13.095; Value: 100V; Green_Lifecycle: Active; SizeY_mm: 1.7; Value1: 0.15A; SizeArea_mm2: 6.545; Io_A: 150mA; SizeZ_mm: 1.35
D21 D27 = CMP-0028526-1: Diode, Schottky, 40 V, 0.5 A, SOD-123; Manufacturer: ON Semiconductor; Io_A: 5dA; Green_Lifecycle: Active; SizeAreaWB_mm2: 13.095; Vr_V: 40V; Green_REACh: Passed; Value1: 0.5A; TJmax_C: 150°C; U/M: EA; Value: 40V; SizeZ_mm: 1.35; SizeX_mm: 3.85; SizeY_mm: 1.7; Vf_V: 5.1dV; Value2: 0.51V; SizeArea_mm2: 6.545; AEC Category: Q101; RJC_CperW: 118
D23-D26 = CMP-0079921-1: LED, Green, SMD; Manufacturer: Lite-On; Io_A: 5mA; SizeAreaWB_mm2: 4.68; Tjmax_C: 85°C; Value1: W; SizeZ_mm: 0.45; SizeX_mm: 1.6; SizeY_mm: 0.8; Vf_V: 2V; SizeArea_mm2: 1.28; Type: AlInGaP
J15 = CMP-0088318-1: MMCX Connector Jack, Female Socket 50Ohm Through Hole, Right Angle Solder; Manufacturer: Samtec; Dielectric Material: PTFE; Shrouded: true; SizeZ_mm: 3.93mm; ContactFinish: Gold; Is Female: yes; AEC Qualified: No; Impedance: 50Ω; Frequency_Fixed: 6GHz
J16 = CMP-0089180-1: Manufacturer: Samtec; ContactFinish: Gold,Nickel; AEC Qualified: No; DUT-Pitch_mm: 1.27mm; SizeZ_mm: 6.38mm; Current_A: 3.4A; Row_Count: 2; Conn Orientation: Vertical; Conn Gender: Male
J17 = CMP-0075665-2: Header, 2.54mm, 5x2, Gold, Black, TH; Manufacturer: Samtec; Pitch_mm: 2.54; Gender: Male; Cert_CSA: Y; Green_REACh: Passed; Shrouded: N; Green_Lifecycle: Active; Row_Count: 2
J19 = CMP-0084558-1: Header, 2.54mm, 2x1, Tin, TH; Manufacturer: Samtec; Cert_UL: Y; Row_Count: 1; Pitch_mm: 2.54; Gender: Male; Current_A: 6.3A; Voltage_V: 550V; Shrouded: N
J20 J21 = CMP-0082603-1: Receptacle, 2.54mm, 3x2, Tin, TH; Manufacturer: TE Connectivity; Pitch_mm: 2.54; Gender: Female; Cert_UL: Y; Row_Count: 2; CompType: Socket Strip
L3-L6 = 74279262: Ferrite Bead, 120 ohm @ 100 MHz, 0.5 A, 0603; Manufacturer: Wurth Elektronik; Value: 120 ohm; Imax_A: 0.5; DCR_ohm: 0.3; Value1: 0.3 ohm; Value2: 0.5A; SizeAreaWB_mm2: 4.68; SizeArea_mm2: 1.28; SizeX_mm: 1.6; SizeY_mm: 0.8; SizeZ_mm: 1; ZTyp@100MHz_Ohm: 120; Ztyp@1GHz_Ohm: 140.994; Green_Lifecycle: Active; Green_REACh: Passed
R40 R59 = CMP-0023143-5: RES, 49.9, 1%, 0.1 W, 0603; Manufacturer: Yageo; Power_W: 100mW; TempCo: 100 ppm/C; Value_Code: 49R9; Value: 49.9; EIA_Code: E96; SizeX_mm: 1.6; SizeY_mm: 0.8; SizeZ_mm: 1; Value2: 0.1W; SizeArea_mm2: 1.28; AEC Qualified: N; VDC_V: 75V; AEC Category: Q200; SizeAreaWB_mm2: 4.68
R41 R56 R67 = CMP-0022895-5: RES, 1.00 k, 1%, 0.1 W, 0603; Manufacturer: Yageo; Power_W: 100mW; TempCo: 100 ppm/C; Value_Code: 1k00; Value: 1.00k; EIA_Code: E96; Res_ohm: 1k; SizeX_mm: 1.6; SizeY_mm: 0.8; SizeZ_mm: 1; Value2: 0.1W; SizeArea_mm2: 1.28; AEC Qualified: N; VDC_V: 75V; AEC Category: Q200; SizeAreaWB_mm2: 4.68
R42 R57 R88 R96 R140 = CMP-0022746-5: as R95 on sheet TIDM-02009_DCDC_C2000
R58 = CMP-0022751-4: RES, 10.0, 1%, 0.1 W, 0603; Manufacturer: Yageo; Power_W: 100mW; TempCo: 100 ppm/C; Value_Code: 10R0; Value: 10.0; EIA_Code: E96; Res_ohm: 10; SizeX_mm: 1.6; SizeY_mm: 0.8; SizeZ_mm: 1; Value2: 0.1W; SizeArea_mm2: 1.28; AEC Qualified: N; VDC_V: 75V; AEC Category: Q200; SizeAreaWB_mm2: 4.68
R62 = CMP-0017094-3: RES, 5.36, 1%, 0.25 W, AEC-Q200 Grade 0, 1206; Manufacturer: Vishay-Dale; Power_W: 250mW; TempCo: 100 ppm/C; Value_Code: 5R36; Value: 5.36; EIA_Code: E96; SizeX_mm: 3.2; SizeY_mm: 1.6; SizeZ_mm: 1.35; Value2: 0.25W; SizeArea_mm2: 5.12; AEC Qualified: Y; VDC_V: 200V; AEC Category: Q200; AEC Grade: 0
R63 R86 = CMP-0022982-5: RES, 2.15 k, 1%, 0.1 W, 0603; Manufacturer: Yageo; Power_W: 100mW; TempCo: 100 ppm/C; Value_Code: 2k15; Value: 2.15k; EIA_Code: E96; SizeX_mm: 1.6; SizeY_mm: 0.8; SizeZ_mm: 1; Value2: 0.1W; SizeArea_mm2: 1.28; AEC Qualified: N; VDC_V: 75V; AEC Category: Q200; SizeAreaWB_mm2: 4.68
R66 = CMP-0022692-3: RES, 22.0 k, 1%, 0.1 W, AEC-Q200 Grade 0, 0603; Manufacturer: Panasonic; Power_W: 100mW; TempCo: 100 ppm/C; Value_Code: 22k0; U/M: EA; Value: 22.0k; Res_ohm: 22k; SizeX_mm: 1.6; SizeY_mm: 0.8; SizeZ_mm: 1; Value2: 0.1W; SizeArea_mm2: 1.28; AEC Qualified: Y; VDC_V: 50V; AEC Grade: 0; AEC Category: Q200
R68 R74 R79 R83 = CMP-0081973-1: as R12 on sheet TIDM-02009_DCDC_C2000
R73 = CMP-0022865-5: RES, 1.05 k, 1%, 0.1 W, 0603; Manufacturer: Yageo; Power_W: 100mW; TempCo: 100 ppm/C; Value_Code: 1k05; Value: 1.05k; EIA_Code: E96; SizeX_mm: 1.6; SizeY_mm: 0.8; SizeZ_mm: 1; Value2: 0.1W; SizeArea_mm2: 1.28; AEC Qualified: N; VDC_V: 75V; AEC Category: Q200; SizeAreaWB_mm2: 4.68
R75 = CMP-0021989-3: RES, 4.99 k, 1%, 0.1 W, 0603; Manufacturer: Bourns; Power_W: 100mW; TempCo: 100 ppm/C; Value_Code: 4k99; U/M: EA; Value: 4.99k; EIA_Code: E96; SizeX_mm: 1.6; SizeY_mm: 0.8; SizeZ_mm: 1; Value2: 0.1W; SizeArea_mm2: 1.28; AEC Category: Q200
R76-R78 = CMP-0017741-3: RES, 845 k, 1%, 0.25 W, AEC-Q200 Grade 0, 1206; Manufacturer: Panasonic; Power_W: 250mW; TempCo: 100 ppm/C; Value: 845k; EIA_Code: E96; SizeX_mm: 3.2; SizeY_mm: 1.6; SizeZ_mm: 1.35; Value2: 0.25W; SizeArea_mm2: 5.12; AEC Qualified: Y; VDC_V: 200V; AEC Category: Q200; AEC Grade: 0; SizeAreaWB_mm2: 10.92
R80 = CMP-0017754-3: RES, 9.09 k, 1%, 0.25 W, AEC-Q200 Grade 0, 1206; Manufacturer: Panasonic; Power_W: 250mW; TempCo: 100 ppm/C; Value_Code: 9k09; Value: 9.09k; EIA_Code: E96; SizeX_mm: 3.2; SizeY_mm: 1.6; SizeZ_mm: 1.35; Value2: 0.25W; SizeArea_mm2: 5.12; AEC Qualified: Y; VDC_V: 200V; AEC Category: Q200; AEC Grade: 0; SizeAreaWB_mm2: 10.92
R81 R94 = CMP-0022816-5: RES, 15.0 k, 1%, 0.1 W, 0603; Manufacturer: Yageo; Power_W: 100mW; TempCo: 100 ppm/C; Value_Code: 15k0; Value: 15.0k; EIA_Code: E96; Res_ohm: 15k; SizeX_mm: 1.6; SizeY_mm: 0.8; SizeZ_mm: 1; Value2: 0.1W; SizeArea_mm2: 1.28; AEC Qualified: N; VDC_V: 75V; AEC Category: Q200; SizeAreaWB_mm2: 4.68
R82 R84 R85 R93 = CMP-0023151-5: RES, 4.64 k, 1%, 0.1 W, 0603; Manufacturer: Yageo; Power_W: 100mW; TempCo: 100 ppm/C; Value_Code: 4k64; Value: 4.64k; EIA_Code: E96; SizeX_mm: 1.6; SizeY_mm: 0.8; SizeZ_mm: 1; Value2: 0.1W; SizeArea_mm2: 1.28; AEC Qualified: N; VDC_V: 75V; AEC Category: Q200; SizeAreaWB_mm2: 4.68
R152 R153 R155 R156 R168-R171 = CRCW06032R21FKEA: RES, 2.21, 1%, 0.1 W, 0603; Manufacturer: Vishay-Dale; CompType: Resistor; Value: 2.21; Value_Code: 2R21; Tolerance_%: 1; Power_W: 0.1; Value2: 0.1W; VDC_V: 75; TempCo: 100 ppm/C; SizeArea_mm2: 1.28; SizeX_mm: 1.6; SizeY_mm: 0.8; EIA_Code: E96; U/M: EA; AEC Category: Q200; Green_Lifecycle: Active; Green_REACh: Passed
R157-R160 R172-R175 = CRCW060310K0FKEA: RES, 10.0 k, 1%, 0.1 W, 0603; Manufacturer: Vishay-Dale; CompType: Resistor; Value: 10.0k; Res_ohm: 10000; Value_Code: 10k0; Tolerance_%: 1; Power_W: 0.1; Value2: 0.1W; VDC_V: 75; TempCo: 100 ppm/C; SizeArea_mm2: 1.28; SizeX_mm: 1.6; SizeY_mm: 0.8; EIA_Code: E96; U/M: EA; AEC Category: Q200; Green_Lifecycle: Active; Green_REACh: Passed
T10 = CMP-0030718-1: Transformer, 475uH, SMT; Manufacturer: Wurth Elektronik; DCR_ohm: 0.31; Lp: 475; Ind_H: 475µH
TP2 TP3 = CMP-0055155-1: Test Point, Compact, Blue, TH; Manufacturer: Keystone; CNHeader: FALSE; Green_Lifecycle: Active; Green_REACh: Passed; ContactFinish: Silver; CT: TRUE
U1 = CMP-0040148-1: Very Low Power, Rail to Rail Out, Negative Rail In, VFB Operational Amplifier, 2.5 to 5.5 V, -40 to 125 degC, 6-pin SOT23 (DBV6), Green (RoHS & no Sb/Br); Manufacturer: Texas Instruments; Iib(Max)(nA): 1000; Io(Typ)(mA): 50; Acl, min stable gain(V/V): 1; Vn at Flatband(Typ)(nV/rtHz): 4.6; Slew Rate(Typ)(V/us): 560; BW @ Acl(MHz): 205; Sub Family: Audio Operational Amplifier, High Output Current Amplifier (>=50mA), High Speed Amplifier (>=50MHz), Low Noise Amp (<=10nV/rtHz), Low Offset Voltage Amplifier (<=500uV), Low Supply Voltage Amplifier (<=2.7V); 3rd Harmonic(dBc): 105; Vio(Max)(mV): 0.4; Settling Time (0.1%)(Typ)(ns): 30; Vs(Min)(V): 2.5; 2nd Harmonic(dBc): 85; Vs(Max)(V): 5.5
U2 = CMP-0036711-1: Single Output High PSRR LDO, 1 A, Fixed 3.3 V Output, 2.7 to 5.5 V Input, 6-pin SOT-223 (DCQ), -40 to 125 degC, Green (RoHS & no Sb/Br); Manufacturer: Texas Instruments; Vin(Max)(V): 5.5; Iq(Typ)(mA): 0.26; Accuracy(%): 2; Fixed Output Options(V): 3.3; Vdo(Typ)(mV): 220; Vin(Min)(V): 2.7; Iout(Max)(A): 1; SubFamily: Single Channel LDO
U3 = CMP-0077327-2: 40-V Ultralow-Iq Low-Dropout Regulator, DBV0005A (SOT-23-5); Manufacturer: Texas Instruments; SizeArea_mm2: 8.12; CompType: IC; SizeAreaWB_mm2: 14.82; SizeY_mm: 2.9; SizeZ_mm: 1.45; SizeX_mm: 2.8; AEC Category: Q200; AEC Qualified: N
U4 = CMP-0076093-1: Automotive Low-Noise 350 mA, 410 kHz Transformer Driver, DBV0005A (SOT-23-5); Manufacturer: Texas Instruments; SizeAreaWB_mm2: 14.82; SizeArea_mm2: 8.12; SizeZ_mm: 1.45; SizeY_mm: 2.9; U/M: EA; CompType: IC; SizeX_mm: 2.8
U5 = CMP-0078341-1: Precision, 2-V Input, Reinforced Isolated Amplifier, DWV0008A (SOIC-8); Alternate Manufacturer: Texas Instruments; SizeAreaWB_mm2: 105.975; SizeZ_mm: 2.8; SizeX_mm: 11.5; SizeY_mm: 5.85; SizeArea_mm2: 67.275; CompType: IC; AEC Qualified: N; AEC Category: Q200
U6 = CMP-0041002-2: 50 MHz, Low-Noise, Single-Supply Rail-to-Rail Operational Amplifier, 2.2 to 5.5 V, -40 to 125 degC, 5-pin SOT23 (DBV5), Green (RoHS & no Sb/Br); Manufacturer: Texas Instruments; Sub Family: High Speed Amplifier (>=50MHz), Low Input Bias Current Amp (<=10pA), Low Noise Amp (<=10nV/rtHz), Low Offset Voltage Amplifier (<=500uV), Low Supply Voltage Amplifier (<=2.7V); Total Supply Voltage(Min)(+5V is 5, +/-5V is 10): 2.2; Slew Rate(Typ)(V/us): 25; Vio (25C)(Max)(mV): 0.2; Total Supply Voltage(Max)(+5V is 5, +/-5V is 10): 5.5; IIB(Max)(pA): 10; Offset Drift(Typ)(uV/C): 1; Iq per channel(Max)(mA): 5; CMRR(Min)(dB): 100
U7 = CMP-0089136-1: Temperature Sensor Analog, Local 0°C ~ 100°C 10mV/°C TO-220-3; Manufacturer: Texas Instruments; Max Supply Voltage: 30V; Standoff Height: 3.3mm; Output Voltage: 6V; TJmax_C: +150°C; Sensor Output: Analog Voltage; Operating Supply Current: 56-91.5uA; SizeZ_mm: 19.55mm; Min Supply Voltage: 4V; AEC Qualified: No; Accuracy: 1.5%
U8 = CMP-0073408-4: Precision Centigrade Temperature Sensor, 3-pin TO-220, Pb-Free; Manufacturer: Texas Instruments; PowerWise: N; PackageTopMarking: NSUZXYTTE#*LM35DT; CompType: Temp Sensor IC; AEC Category: Q200; SizeAreaWB_mm2: 80.26; SizeArea_mm2: 46.74; SizeX_mm: 10.16; SizeY_mm: 4.6; SizeZ_mm: 19.65
U14 U15 U17 U18 = CMP-0073915-1: Automotive grade Dual 5-A High-Speed Low-Side Gate Driver With Negative Input Voltage Capability, D0008A (SOIC-8); Alternate Manufacturer: Texas Instruments; SizeAreaWB_mm2: 56.58; U/M: EA; SizeZ_mm: 1.75; SizeX_mm: 4.9; SizeY_mm: 6.2; SizeArea_mm2: 30.38; CompType: IC

## Sheet TIDM-02009_DCDC_Hardware.SchDoc
size A3; PageSetup: Record=PageOptions¦CenterHorizontal=True¦CenterVertical=True¦PrintScale=0.69¦XCorrection=1.00¦YCorrection=1.00¦PrintKind=0¦BorderSize=5000000¦LeftOffset=0¦BottomOffset=0¦Orientation=2¦PaperLength=1000¦PaperWidth=1000¦Scale=100¦PaperSource=15¦PrintQuality=600¦MediaType=1¦DitherType=10¦PaperKind=Letter¦PrintScaleMode=1
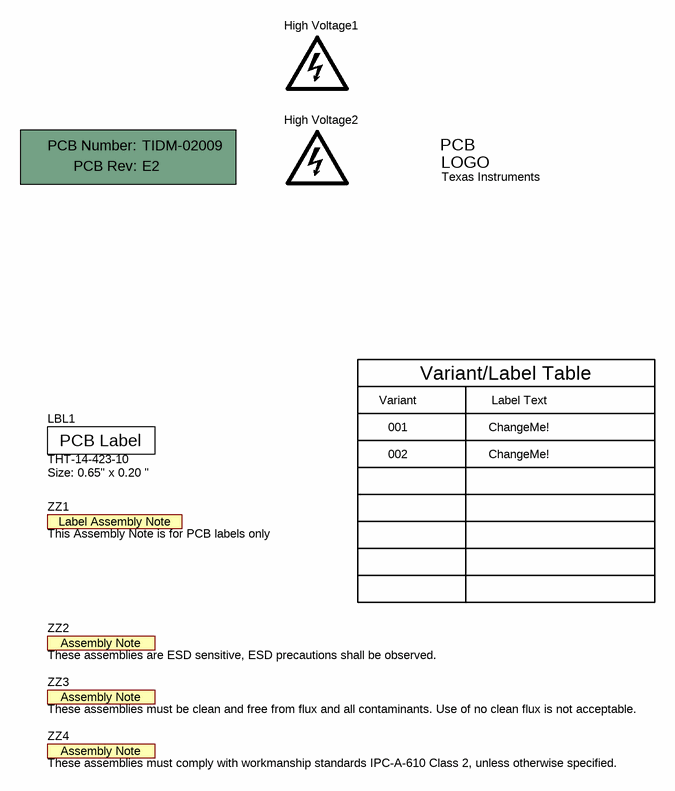
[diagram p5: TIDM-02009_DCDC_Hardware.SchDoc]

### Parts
!PCB1  Printed Circuit Board  (value not drawn)  (mechanical)
High_Voltage1  DANGER HIGH VOLTAGE  [IEC_HighVoltage_Medium]  (value not drawn)  (no BOM)
High_Voltage2  DANGER HIGH VOLTAGE  [IEC_HighVoltage_Medium]  (value not drawn)  (no BOM)
LBL1  THT-14-423-10  Note: Size: 0.65" x 0.20 "  [Label_650x200]
Logo1  Texas Instruments  [TI_Stacked_Overlay_Small]  (no BOM)
ZZ1  This Assembly Note is for PCB labels only  [AssemblyNoteLabel]  (no BOM)
ZZ2  These assemblies are ESD sensitive, ESD precautions shall be observed.  [AssemblyNote]  (no BOM)
ZZ3  These assemblies must be clean and free from flux and all contaminants. Use of no clean flux is not acceptable.  [AssemblyNote]  (no BOM)
ZZ4  These assemblies must comply with workmanship standards IPC-A-610 Class 2, unless otherwise specified.  [AssemblyNote]  (no BOM)

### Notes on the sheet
- Variant/Label Table
- Variant
- 001
- Label Text
- ChangeMe!
- 002

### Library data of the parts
!PCB1 = CMP-0003618-2: Manufacturer: Any; PartNumber: TIDM-02009
High_Voltage1 High_Voltage2 = CMP-0074835-1: IEC 61010-1 High Voltage Warning; SymbolCreator: a0412235
LBL1 = CMP-0003625-1: Thermal Transfer Printable Labels, 0.650" W x 0.200" H - 10,000 per roll; Manufacturer: Brady; CompType: Label
Logo1 = CMP-0074838-1: Texas Instrument Corporate Signature; SymbolCreator: a0412235; Lib Reference: TI_Logo; Library Reference: Logo
ZZ1 = CMP-0003616-3
ZZ2 = CMP-0077236-1
ZZ3 = CMP-0077237-1
ZZ4 = CMP-0077238-1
